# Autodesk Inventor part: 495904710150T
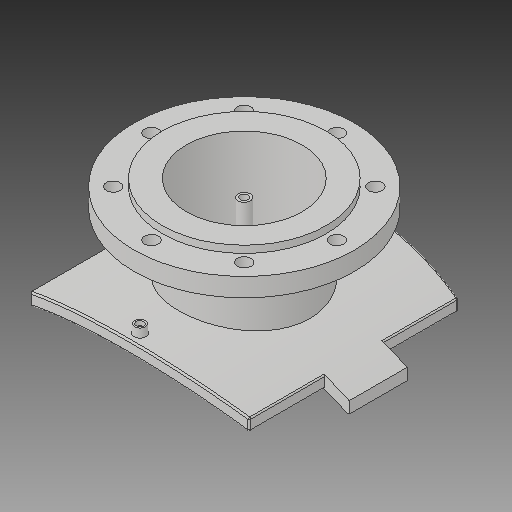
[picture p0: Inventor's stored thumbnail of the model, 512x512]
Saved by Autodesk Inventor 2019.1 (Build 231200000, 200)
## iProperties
Created: 2017-10
Part Number: 495904710150T
Material: Generic
Description: PLASSON FLANGED BRANCH SADDLE 450-800X150
Document SubType Name: Modeling
Designer: KIM
Mass: 2339.99 g
Surface Area: 3251.55 cm^2
Volume: 2339.99 cm^3
Density: 1 g/cm^3
Appearance: Default
Author: KIM
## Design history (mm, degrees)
derived "495904_495903.ipt"
feature "Solid1::495904_495903.ipt"
feature "Solid2::495904_495903.ipt"
tag "TaggingFeature1"
body "Solid1"
other parameters: "d1" = 15, "d2" = 283.5, "d4" = 0, "d6" = 75, "d7" = 0, "d12" = 425.6, "d13" = 14, "d14" = 135, "d16" = 5 deg, "d18" = 4, "d19" = 14, "d20" = 0, "d21" = 3, "d22" = 0, "d23" = 536, "d36" = 135, "d38" = 0, "d39" = 2, "d42" = 212, "d43" = 285, "d44" = 96.8, "d46" = 169.6, "d47" = 16, "d48" = 10.4, "d49" = 84.7, "d51" = 816, "d53" = 0, "d54" = 18, "d57" = 0, "d59" = 360 deg, "d61" = 24, "d63" = 0, "d66" = 121, "d67" = 15, "d68" = 60.5, "d70" = 0, "d71" = 2, "d72" = 315, "d_1" = 212, "B_" = 315, "H_" = 121, "x_" = 15, "D_" = 16, "D_1" = 285, "t_" = 24, "s_" = 18
